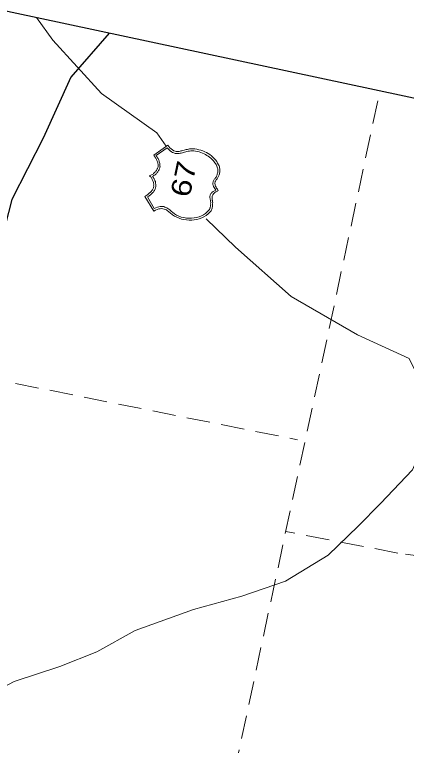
# Model space of a CAD drawing. Extents: x 2363411 to 2369126, y 6976878 to 6988319.
# Drawn here: x 2366047.6 to 2366148.5, y 6977167 to 6977355.3 of the extents above; entities that cross this region are included whole.
import ezdxf

# ---------------------------------------------------------------- set-up
doc = ezdxf.new("R2010")
doc.units = 0
doc.header["$LTSCALE"] = 2
doc.linetypes.add('MEDIUM_DASHED', pattern=[4.5, 3, -1.5])
doc.layers.add('62', color=7, linetype='Continuous', lineweight=13)
doc.layers.add('63', color=7, linetype='Continuous', lineweight=13)

msp = doc.modelspace()

# ---------------------------------------------------------------- linework, layer by layer
at = {"layer": '62', "linetype": 'MEDIUM_DASHED'}
for p, q in [((2366047.7, 6976895.971), (2366141.643, 6977335.641)), ((2365844.834, 6977300.827), (2366120.392, 6977245.768))]:
    msp.add_line(p, q, dxfattribs=at)
at = {"layer": '62'}
msp.add_line((2366084.159, 6977324.84), (2366086.62, 6977321.394), dxfattribs=at)
at = {"layer": '62', "lineweight": 25}
for points in [[(2365678.211, 6976974.92), (2366133.213, 6976877.7), (2366227.156, 6977317.368), (2365772.152, 6977414.588)], [(2366071.953, 6977350.532), (2366062.056, 6977339.206), (2366054.911, 6977323.43), (2366046.839, 6977307.62), (2366040.832, 6977284.562), (2366037.039, 6977271.012), (2366035.805, 6977261.035), (2366034.117, 6977243.885), (2366031.631, 6977232.244), (2366030.337, 6977223.387)]]:
    msp.add_lwpolyline(points, dxfattribs=at)
at = {"layer": '62'}
for points in [[(2366053.162, 6977354.543), (2366057.393, 6977348.718), (2366069.909, 6977334.93), (2366084.159, 6977324.84)], [(2366083.387, 6977304.644), (2366081.122, 6977308.465), (2366081.357, 6977308.599), (2366081.594, 6977308.733), (2366081.789, 6977308.897), (2366082.002, 6977309.034), (2366082.173, 6977309.185), (2366082.346, 6977309.353), (2366082.512, 6977309.479), (2366082.686, 6977309.648), (2366082.833, 6977309.801), (2366082.937, 6977309.965), (2366083.067, 6977310.144), (2366083.148, 6977310.311), (2366083.257, 6977310.494), (2366083.335, 6977310.639), (2366083.377, 6977310.838), (2366083.395, 6977311.039), (2366083.404, 6977311.174), (2366083.371, 6977311.343), (2366083.385, 6977311.524), (2366083.378, 6977311.709), (2366083.329, 6977311.906), (2366083.295, 6977312.073), (2366083.246, 6977312.267), (2366083.196, 6977312.462), (2366083.101, 6977312.666), (2366083.025, 6977312.844), (2366082.901, 6977313.032), (2366082.846, 6977313.204), (2366082.698, 6977313.374), (2366082.568, 6977313.517), (2366082.411, 6977313.642), (2366082.253, 6977313.768), (2366082.453, 6977313.84), (2366082.658, 6977313.937), (2366082.857, 6977314.007), (2366083.043, 6977314.129), (2366083.226, 6977314.227), (2366083.375, 6977314.379), (2366083.54, 6977314.505), (2366083.686, 6977314.658), (2366083.814, 6977314.815), (2366083.961, 6977314.968), (2366084.07, 6977315.151), (2366084.173, 6977315.313), (2366084.262, 6977315.525), (2366084.364, 6977315.665), (2366084.453, 6977315.875), (2366084.496, 6977316.072), (2366084.529, 6977316.227), (2366084.566, 6977316.403), (2366084.533, 6977316.569), (2366084.532, 6977316.778), (2366084.477, 6977316.952), (2366084.447, 6977317.142), (2366084.372, 6977317.32), (2366084.321, 6977317.515), (2366084.222, 6977317.697), (2366084.132, 6977317.923), (2366084.033, 6977318.104), (2366083.939, 6977318.31), (2366083.795, 6977318.5), (2366083.682, 6977318.731), (2366083.535, 6977318.903), (2366083.397, 6977319.115), (2366087.028, 6977321.675), (2366087.25, 6977321.329), (2366087.52, 6977320.972), (2366087.851, 6977320.693), (2366088.193, 6977320.46), (2366088.535, 6977320.228), (2366088.877, 6977320.106), (2366089.158, 6977320.025), (2366089.362, 6977320.002), (2366089.543, 6977319.988), (2366089.736, 6977320.039), (2366089.945, 6977320.039), (2366090.167, 6977320.106), (2366090.408, 6977320.169), (2366090.654, 6977320.235), (2366090.919, 6977320.291), (2366091.21, 6977320.368), (2366091.48, 6977320.449), (2366091.751, 6977320.529), (2366092.06, 6977320.577), (2366092.326, 6977320.635), (2366092.615, 6977320.687), (2366092.871, 6977320.702), (2366093.131, 6977320.741), (2366093.399, 6977320.706), (2366093.969, 6977320.676), (2366094.53, 6977320.604), (2366095.035, 6977320.494), (2366095.553, 6977320.336), (2366096.048, 6977320.183), (2366096.531, 6977319.967), (2366096.992, 6977319.752), (2366097.445, 6977319.496), (2366097.868, 6977319.222), (2366098.262, 6977318.908)], [(2366098.788, 6977317.597), (2366098.582, 6977317.823), (2366098.338, 6977318.084), (2366098.064, 6977318.304), (2366097.771, 6977318.553), (2366097.451, 6977318.779), (2366097.111, 6977319.015), (2366096.746, 6977319.253), (2366096.375, 6977319.448), (2366095.954, 6977319.63), (2366095.528, 6977319.789), (2366095.098, 6977319.928), (2366094.636, 6977320.027), (2366094.146, 6977320.109), (2366093.718, 6977320.153), (2366093.313, 6977320.193), (2366092.943, 6977320.182), (2366092.588, 6977320.141), (2366092.258, 6977320.097), (2366091.921, 6977320.032), (2366091.629, 6977319.957), (2366091.333, 6977319.857), (2366091.035, 6977319.761), (2366090.77, 6977319.701), (2366090.5, 6977319.622), (2366090.235, 6977319.564), (2366089.97, 6977319.506), (2366089.711, 6977319.492), (2366089.478, 6977319.472), (2366089.204, 6977319.484), (2366088.895, 6977319.55), (2366088.554, 6977319.667), (2366088.238, 6977319.807), (2366087.927, 6977319.963), (2366087.626, 6977320.166), (2366087.359, 6977320.43), (2366087.114, 6977320.691), (2366086.875, 6977320.969), (2366084.009, 6977318.962), (2366084.128, 6977318.775), (2366084.256, 6977318.608), (2366084.4, 6977318.418), (2366084.498, 6977318.237), (2366084.593, 6977318.031), (2366084.686, 6977317.827), (2366084.76, 6977317.629), (2366084.83, 6977317.428), (2366084.876, 6977317.212), (2366084.948, 6977317.012), (2366084.993, 6977316.794), (2366085.006, 6977316.632), (2366085.007, 6977316.425), (2366084.997, 6977316.266), (2366085.012, 6977316.123), (2366084.981, 6977315.969), (2366084.948, 6977315.814), (2366084.882, 6977315.622), (2366084.822, 6977315.452), (2366084.762, 6977315.279), (2366084.655, 6977315.093), (2366084.555, 6977314.955), (2366084.447, 6977314.772), (2366084.321, 6977314.614), (2366084.222, 6977314.474), (2366084.065, 6977314.279), (2366083.927, 6977314.169), (2366083.784, 6977314.04), (2366083.617, 6977313.892), (2366083.438, 6977313.813), (2366083.273, 6977313.689), (2366083.046, 6977313.601), (2366083.194, 6977313.43), (2366083.326, 6977313.287), (2366083.424, 6977313.105), (2366083.505, 6977312.948), (2366083.588, 6977312.791), (2366083.648, 6977312.642), (2366083.719, 6977312.444), (2366083.807, 6977312.311), (2366083.811, 6977312.124), (2366083.867, 6977311.953), (2366083.879, 6977311.786), (2366083.911, 6977311.62), (2366083.901, 6977311.461), (2366083.929, 6977311.271), (2366083.919, 6977311.113), (2366083.909, 6977310.952), (2366083.891, 6977310.772), (2366083.844, 6977310.553), (2366083.764, 6977310.388), (2366083.671, 6977310.174), (2366083.563, 6977309.991), (2366083.428, 6977309.789), (2366083.294, 6977309.59), (2366083.15, 6977309.457), (2366082.995, 6977309.261), (2366082.843, 6977309.087), (2366082.673, 6977308.94), (2366082.484, 6977308.818), (2366082.31, 6977308.649), (2366082.101, 6977308.532)], [(2366098.262, 6977318.908), (2366098.626, 6977318.575), (2366098.967, 6977318.226), (2366099.303, 6977317.857), (2366099.601, 6977317.426), (2366099.855, 6977317.001), (2366100.106, 6977316.557), (2366100.213, 6977316.303), (2366100.299, 6977316.056), (2366100.36, 6977315.811), (2366100.378, 6977315.579), (2366100.425, 6977315.362), (2366100.424, 6977315.131), (2366100.416, 6977314.879), (2366100.395, 6977314.679), (2366100.371, 6977314.453), (2366100.3, 6977314.237), (2366100.258, 6977314.042), (2366100.174, 6977313.851), (2366100.058, 6977313.647), (2366099.999, 6977313.473), (2366099.895, 6977313.314), (2366099.793, 6977313.149), (2366099.688, 6977312.988), (2366099.589, 6977312.847), (2366099.466, 6977312.714), (2366099.392, 6977312.566), (2366099.314, 6977312.423), (2366099.233, 6977312.257), (2366099.179, 6977312.107), (2366099.141, 6977311.93), (2366099.148, 6977311.745), (2366099.176, 6977311.555), (2366099.243, 6977311.334), (2366099.315, 6977311.135), (2366099.441, 6977310.854), (2366099.566, 6977310.598), (2366099.787, 6977310.32), (2366100.012, 6977309.973), (2366099.696, 6977309.787), (2366099.423, 6977309.594), (2366099.16, 6977309.444), (2366098.988, 6977309.272), (2366098.818, 6977309.124), (2366098.669, 6977308.972), (2366098.593, 6977308.827), (2366098.494, 6977308.688), (2366098.443, 6977308.558), (2366098.41, 6977308.406), (2366098.408, 6977308.289), (2366098.419, 6977308.128), (2366098.413, 6977307.992), (2366098.429, 6977307.849), (2366098.463, 6977307.683), (2366098.473, 6977307.519), (2366098.518, 6977307.395), (2366098.522, 6977307.21), (2366098.552, 6977307.019), (2366098.579, 6977306.829), (2366098.56, 6977306.625), (2366098.567, 6977306.441), (2366098.562, 6977306.211), (2366098.547, 6977306.031), (2366098.499, 6977305.81), (2366098.462, 6977305.634), (2366098.416, 6977305.414), (2366098.341, 6977305.177), (2366098.233, 6977304.993), (2366098.142, 6977304.782), (2366098.009, 6977304.581), (2366097.848, 6977304.384), (2366097.412, 6977303.95), (2366096.889, 6977303.552), (2366096.335, 6977303.21), (2366095.744, 6977302.923), (2366095.118, 6977302.689), (2366094.508, 6977302.521), (2366093.845, 6977302.432), (2366093.163, 6977302.371), (2366092.518, 6977302.369), (2366091.856, 6977302.394), (2366091.188, 6977302.494), (2366090.55, 6977302.631), (2366089.905, 6977302.836), (2366089.332, 6977303.075), (2366088.756, 6977303.382), (2366088.23, 6977303.723), (2366088.029, 6977303.856), (2366087.832, 6977304.015), (2366087.618, 6977304.2), (2366087.408, 6977304.406), (2366087.17, 6977304.572), (2366086.934, 6977304.759), (2366086.677, 6977304.955), (2366086.399, 6977305.057), (2366086.103, 6977305.19), (2366085.775, 6977305.26), (2366085.466, 6977305.326), (2366085.09, 6977305.292), (2366084.714, 6977305.256), (2366084.271, 6977305.121)], [(2366081.761, 6977308.331), (2366083.533, 6977305.326), (2366083.968, 6977305.532), (2366084.362, 6977305.654), (2366084.73, 6977305.76), (2366085.066, 6977305.827), (2366085.41, 6977305.823), (2366085.711, 6977305.826), (2366085.984, 6977305.815), (2366086.262, 6977305.71), (2366086.533, 6977305.583), (2366086.789, 6977305.481), (2366087.056, 6977305.332), (2366087.29, 6977305.143), (2366087.509, 6977304.984), (2366087.747, 6977304.794), (2366087.952, 6977304.588), (2366088.186, 6977304.379), (2366088.718, 6977303.965), (2366089.293, 6977303.635), (2366089.852, 6977303.354), (2366090.477, 6977303.151), (2366091.134, 6977302.988), (2366091.797, 6977302.869), (2366092.459, 6977302.842), (2366093.109, 6977302.865), (2366093.79, 6977302.926), (2366094.439, 6977303.063), (2366095.073, 6977303.228), (2366095.675, 6977303.468), (2366096.195, 6977303.75), (2366096.748, 6977304.067), (2366097.197, 6977304.454), (2366097.609, 6977304.873), (2366097.654, 6977304.978), (2366097.744, 6977305.075), (2366097.822, 6977305.218), (2366097.859, 6977305.396), (2366097.887, 6977305.527), (2366097.947, 6977305.7), (2366097.985, 6977305.875), (2366098.001, 6977306.055), (2366098.042, 6977306.253), (2366098.08, 6977306.429), (2366098.052, 6977306.619), (2366098.067, 6977306.8), (2366098.082, 6977306.981), (2366098.049, 6977307.149), (2366098.038, 6977307.313), (2366098.022, 6977307.454), (2366097.968, 6977307.627), (2366097.93, 6977307.772), (2366097.892, 6977307.919), (2366097.877, 6977308.059), (2366097.849, 6977308.249), (2366097.85, 6977308.366), (2366097.859, 6977308.523), (2366097.892, 6977308.678), (2366097.948, 6977308.829), (2366098.039, 6977309.037), (2366098.139, 6977309.177), (2366098.307, 6977309.327), (2366098.464, 6977309.523), (2366098.732, 6977309.697), (2366099.008, 6977309.912), (2366099.346, 6977310.093), (2366099.105, 6977310.466), (2366098.94, 6977310.779), (2366098.79, 6977311.042), (2366098.687, 6977311.316), (2366098.646, 6977311.556), (2366098.617, 6977311.744), (2366098.616, 6977311.951), (2366098.658, 6977312.15), (2366098.718, 6977312.322), (2366098.772, 6977312.472), (2366098.876, 6977312.631), (2366098.98, 6977312.795), (2366099.082, 6977312.955), (2366099.205, 6977313.091), (2366099.312, 6977313.275), (2366099.443, 6977313.455), (2366099.529, 6977313.643), (2366099.659, 6977313.822), (2366099.706, 6977314.043), (2366099.771, 6977314.236), (2366099.841, 6977314.45), (2366099.865, 6977314.676), (2366099.885, 6977314.878), (2366099.911, 6977315.104), (2366099.885, 6977315.314), (2366099.889, 6977315.546), (2366099.801, 6977315.772), (2366099.759, 6977316.009), (2366099.666, 6977316.215), (2366099.58, 6977316.463), (2366099.445, 6977316.698), (2366099.312, 6977316.933), (2366099.168, 6977317.124), (2366098.965, 6977317.353), (2366098.788, 6977317.597)], [(2366082.101, 6977308.532), (2366081.92, 6977308.432), (2366081.761, 6977308.331)], [(2366084.271, 6977305.121), (2366083.842, 6977304.937), (2366083.387, 6977304.644)], [(2366096.932, 6977302.67), (2366104.486, 6977295.374), (2366118.795, 6977282.65), (2366135.856, 6977272.793), (2366149.213, 6977266.718), (2366158.553, 6977247.649), (2366168.364, 6977245.412), (2366174.148, 6977227.473), (2366180.022, 6977212.757), (2366183.73, 6977195.536), (2366183.185, 6977172.733), (2366183.468, 6977153.162), (2366184.402, 6977131.701), (2366184.733, 6977118.813)], [(2366165.563, 6977270.54), (2366160.925, 6977263.273), (2366157.11, 6977254.238), (2366150.016, 6977238.06), (2366141.756, 6977229.335), (2366136.001, 6977223.497), (2366128.351, 6977216.018), (2366117.334, 6977209.377), (2366106.082, 6977205.501), (2366093.663, 6977202.078), (2366078.646, 6977196.636), (2366068.712, 6977191.165), (2366059.206, 6977187.374), (2366047.443, 6977183.467), (2366041.833, 6977180.594), (2366027.902, 6977176.345)]]:
    msp.add_lwpolyline(points, dxfattribs=at)
at = {"layer": '62', "linetype": 'MEDIUM_DASHED'}
msp.add_lwpolyline([(2366203.686, 6977207.519), (2366189.861, 6977210.657), (2366146.236, 6977216.593), (2366117.386, 6977222.114)], dxfattribs=at)
at = {"layer": '63', "linetype": 'MEDIUM_DASHED'}
for p, q in [((2366047.7, 6976895.971), (2366141.643, 6977335.641)), ((2365844.834, 6977300.827), (2366120.392, 6977245.768))]:
    msp.add_line(p, q, dxfattribs=at)
at = {"layer": '63'}
msp.add_line((2366084.159, 6977324.84), (2366086.62, 6977321.394), dxfattribs=at)
at = {"layer": '63', "lineweight": 25}
for points in [[(2365678.211, 6976974.92), (2366133.213, 6976877.7), (2366227.156, 6977317.368), (2365772.152, 6977414.588)], [(2366071.953, 6977350.532), (2366062.056, 6977339.206), (2366054.911, 6977323.43), (2366046.839, 6977307.62), (2366040.832, 6977284.562), (2366037.039, 6977271.012), (2366035.805, 6977261.035), (2366034.117, 6977243.885), (2366031.631, 6977232.244), (2366030.337, 6977223.387)]]:
    msp.add_lwpolyline(points, dxfattribs=at)
at = {"layer": '63'}
for points in [[(2366053.162, 6977354.543), (2366057.393, 6977348.718), (2366069.909, 6977334.93), (2366084.159, 6977324.84)], [(2366083.387, 6977304.644), (2366081.122, 6977308.465), (2366081.357, 6977308.599), (2366081.594, 6977308.733), (2366081.789, 6977308.897), (2366082.002, 6977309.034), (2366082.173, 6977309.185), (2366082.346, 6977309.353), (2366082.512, 6977309.479), (2366082.686, 6977309.648), (2366082.833, 6977309.801), (2366082.937, 6977309.965), (2366083.067, 6977310.144), (2366083.148, 6977310.311), (2366083.257, 6977310.494), (2366083.335, 6977310.639), (2366083.377, 6977310.838), (2366083.395, 6977311.039), (2366083.404, 6977311.174), (2366083.371, 6977311.343), (2366083.385, 6977311.524), (2366083.378, 6977311.709), (2366083.329, 6977311.906), (2366083.295, 6977312.073), (2366083.246, 6977312.267), (2366083.196, 6977312.462), (2366083.101, 6977312.666), (2366083.025, 6977312.844), (2366082.901, 6977313.032), (2366082.846, 6977313.204), (2366082.698, 6977313.374), (2366082.568, 6977313.517), (2366082.411, 6977313.642), (2366082.253, 6977313.768), (2366082.453, 6977313.84), (2366082.658, 6977313.937), (2366082.857, 6977314.007), (2366083.043, 6977314.129), (2366083.226, 6977314.227), (2366083.375, 6977314.379), (2366083.54, 6977314.505), (2366083.686, 6977314.658), (2366083.814, 6977314.815), (2366083.961, 6977314.968), (2366084.07, 6977315.151), (2366084.173, 6977315.313), (2366084.262, 6977315.525), (2366084.364, 6977315.665), (2366084.453, 6977315.875), (2366084.496, 6977316.072), (2366084.529, 6977316.227), (2366084.566, 6977316.403), (2366084.533, 6977316.569), (2366084.532, 6977316.778), (2366084.477, 6977316.952), (2366084.447, 6977317.142), (2366084.372, 6977317.32), (2366084.321, 6977317.515), (2366084.222, 6977317.697), (2366084.132, 6977317.923), (2366084.033, 6977318.104), (2366083.939, 6977318.31), (2366083.795, 6977318.5), (2366083.682, 6977318.731), (2366083.535, 6977318.903), (2366083.397, 6977319.115), (2366087.028, 6977321.675), (2366087.25, 6977321.329), (2366087.52, 6977320.972), (2366087.851, 6977320.693), (2366088.193, 6977320.46), (2366088.535, 6977320.228), (2366088.877, 6977320.106), (2366089.158, 6977320.025), (2366089.362, 6977320.002), (2366089.543, 6977319.988), (2366089.736, 6977320.039), (2366089.945, 6977320.039), (2366090.167, 6977320.106), (2366090.408, 6977320.169), (2366090.654, 6977320.235), (2366090.919, 6977320.291), (2366091.21, 6977320.368), (2366091.48, 6977320.449), (2366091.751, 6977320.529), (2366092.06, 6977320.577), (2366092.326, 6977320.635), (2366092.615, 6977320.687), (2366092.871, 6977320.702), (2366093.131, 6977320.741), (2366093.399, 6977320.706), (2366093.969, 6977320.676), (2366094.53, 6977320.604), (2366095.035, 6977320.494), (2366095.553, 6977320.336), (2366096.048, 6977320.183), (2366096.531, 6977319.967), (2366096.992, 6977319.752), (2366097.445, 6977319.496), (2366097.868, 6977319.222), (2366098.262, 6977318.908)], [(2366098.788, 6977317.597), (2366098.582, 6977317.823), (2366098.338, 6977318.084), (2366098.064, 6977318.304), (2366097.771, 6977318.553), (2366097.451, 6977318.779), (2366097.111, 6977319.015), (2366096.746, 6977319.253), (2366096.375, 6977319.448), (2366095.954, 6977319.63), (2366095.528, 6977319.789), (2366095.098, 6977319.928), (2366094.636, 6977320.027), (2366094.146, 6977320.109), (2366093.718, 6977320.153), (2366093.313, 6977320.193), (2366092.943, 6977320.182), (2366092.588, 6977320.141), (2366092.258, 6977320.097), (2366091.921, 6977320.032), (2366091.629, 6977319.957), (2366091.333, 6977319.857), (2366091.035, 6977319.761), (2366090.77, 6977319.701), (2366090.5, 6977319.622), (2366090.235, 6977319.564), (2366089.97, 6977319.506), (2366089.711, 6977319.492), (2366089.478, 6977319.472), (2366089.204, 6977319.484), (2366088.895, 6977319.55), (2366088.554, 6977319.667), (2366088.238, 6977319.807), (2366087.927, 6977319.963), (2366087.626, 6977320.166), (2366087.359, 6977320.43), (2366087.114, 6977320.691), (2366086.875, 6977320.969), (2366084.009, 6977318.962), (2366084.128, 6977318.775), (2366084.256, 6977318.608), (2366084.4, 6977318.418), (2366084.498, 6977318.237), (2366084.593, 6977318.031), (2366084.686, 6977317.827), (2366084.76, 6977317.629), (2366084.83, 6977317.428), (2366084.876, 6977317.212), (2366084.948, 6977317.012), (2366084.993, 6977316.794), (2366085.006, 6977316.632), (2366085.007, 6977316.425), (2366084.997, 6977316.266), (2366085.012, 6977316.123), (2366084.981, 6977315.969), (2366084.948, 6977315.814), (2366084.882, 6977315.622), (2366084.822, 6977315.452), (2366084.762, 6977315.279), (2366084.655, 6977315.093), (2366084.555, 6977314.955), (2366084.447, 6977314.772), (2366084.321, 6977314.614), (2366084.222, 6977314.474), (2366084.065, 6977314.279), (2366083.927, 6977314.169), (2366083.784, 6977314.04), (2366083.617, 6977313.892), (2366083.438, 6977313.813), (2366083.273, 6977313.689), (2366083.046, 6977313.601), (2366083.194, 6977313.43), (2366083.326, 6977313.287), (2366083.424, 6977313.105), (2366083.505, 6977312.948), (2366083.588, 6977312.791), (2366083.648, 6977312.642), (2366083.719, 6977312.444), (2366083.807, 6977312.311), (2366083.811, 6977312.124), (2366083.867, 6977311.953), (2366083.879, 6977311.786), (2366083.911, 6977311.62), (2366083.901, 6977311.461), (2366083.929, 6977311.271), (2366083.919, 6977311.113), (2366083.909, 6977310.952), (2366083.891, 6977310.772), (2366083.844, 6977310.553), (2366083.764, 6977310.388), (2366083.671, 6977310.174), (2366083.563, 6977309.991), (2366083.428, 6977309.789), (2366083.294, 6977309.59), (2366083.15, 6977309.457), (2366082.995, 6977309.261), (2366082.843, 6977309.087), (2366082.673, 6977308.94), (2366082.484, 6977308.818), (2366082.31, 6977308.649), (2366082.101, 6977308.532)], [(2366098.262, 6977318.908), (2366098.626, 6977318.575), (2366098.967, 6977318.226), (2366099.303, 6977317.857), (2366099.601, 6977317.426), (2366099.855, 6977317.001), (2366100.106, 6977316.557), (2366100.213, 6977316.303), (2366100.299, 6977316.056), (2366100.36, 6977315.811), (2366100.378, 6977315.579), (2366100.425, 6977315.362), (2366100.424, 6977315.131), (2366100.416, 6977314.879), (2366100.395, 6977314.679), (2366100.371, 6977314.453), (2366100.3, 6977314.237), (2366100.258, 6977314.042), (2366100.174, 6977313.851), (2366100.058, 6977313.647), (2366099.999, 6977313.473), (2366099.895, 6977313.314), (2366099.793, 6977313.149), (2366099.688, 6977312.988), (2366099.589, 6977312.847), (2366099.466, 6977312.714), (2366099.392, 6977312.566), (2366099.314, 6977312.423), (2366099.233, 6977312.257), (2366099.179, 6977312.107), (2366099.141, 6977311.93), (2366099.148, 6977311.745), (2366099.176, 6977311.555), (2366099.243, 6977311.334), (2366099.315, 6977311.135), (2366099.441, 6977310.854), (2366099.566, 6977310.598), (2366099.787, 6977310.32), (2366100.012, 6977309.973), (2366099.696, 6977309.787), (2366099.423, 6977309.594), (2366099.16, 6977309.444), (2366098.988, 6977309.272), (2366098.818, 6977309.124), (2366098.669, 6977308.972), (2366098.593, 6977308.827), (2366098.494, 6977308.688), (2366098.443, 6977308.558), (2366098.41, 6977308.406), (2366098.408, 6977308.289), (2366098.419, 6977308.128), (2366098.413, 6977307.992), (2366098.429, 6977307.849), (2366098.463, 6977307.683), (2366098.473, 6977307.519), (2366098.518, 6977307.395), (2366098.522, 6977307.21), (2366098.552, 6977307.019), (2366098.579, 6977306.829), (2366098.56, 6977306.625), (2366098.567, 6977306.441), (2366098.562, 6977306.211), (2366098.547, 6977306.031), (2366098.499, 6977305.81), (2366098.462, 6977305.634), (2366098.416, 6977305.414), (2366098.341, 6977305.177), (2366098.233, 6977304.993), (2366098.142, 6977304.782), (2366098.009, 6977304.581), (2366097.848, 6977304.384), (2366097.412, 6977303.95), (2366096.889, 6977303.552), (2366096.335, 6977303.21), (2366095.744, 6977302.923), (2366095.118, 6977302.689), (2366094.508, 6977302.521), (2366093.845, 6977302.432), (2366093.163, 6977302.371), (2366092.518, 6977302.369), (2366091.856, 6977302.394), (2366091.188, 6977302.494), (2366090.55, 6977302.631), (2366089.905, 6977302.836), (2366089.332, 6977303.075), (2366088.756, 6977303.382), (2366088.23, 6977303.723), (2366088.029, 6977303.856), (2366087.832, 6977304.015), (2366087.618, 6977304.2), (2366087.408, 6977304.406), (2366087.17, 6977304.572), (2366086.934, 6977304.759), (2366086.677, 6977304.955), (2366086.399, 6977305.057), (2366086.103, 6977305.19), (2366085.775, 6977305.26), (2366085.466, 6977305.326), (2366085.09, 6977305.292), (2366084.714, 6977305.256), (2366084.271, 6977305.121)], [(2366081.761, 6977308.331), (2366083.533, 6977305.326), (2366083.968, 6977305.532), (2366084.362, 6977305.654), (2366084.73, 6977305.76), (2366085.066, 6977305.827), (2366085.41, 6977305.823), (2366085.711, 6977305.826), (2366085.984, 6977305.815), (2366086.262, 6977305.71), (2366086.533, 6977305.583), (2366086.789, 6977305.481), (2366087.056, 6977305.332), (2366087.29, 6977305.143), (2366087.509, 6977304.984), (2366087.747, 6977304.794), (2366087.952, 6977304.588), (2366088.186, 6977304.379), (2366088.718, 6977303.965), (2366089.293, 6977303.635), (2366089.852, 6977303.354), (2366090.477, 6977303.151), (2366091.134, 6977302.988), (2366091.797, 6977302.869), (2366092.459, 6977302.842), (2366093.109, 6977302.865), (2366093.79, 6977302.926), (2366094.439, 6977303.063), (2366095.073, 6977303.228), (2366095.675, 6977303.468), (2366096.195, 6977303.75), (2366096.748, 6977304.067), (2366097.197, 6977304.454), (2366097.609, 6977304.873), (2366097.654, 6977304.978), (2366097.744, 6977305.075), (2366097.822, 6977305.218), (2366097.859, 6977305.396), (2366097.887, 6977305.527), (2366097.947, 6977305.7), (2366097.985, 6977305.875), (2366098.001, 6977306.055), (2366098.042, 6977306.253), (2366098.08, 6977306.429), (2366098.052, 6977306.619), (2366098.067, 6977306.8), (2366098.082, 6977306.981), (2366098.049, 6977307.149), (2366098.038, 6977307.313), (2366098.022, 6977307.454), (2366097.968, 6977307.627), (2366097.93, 6977307.772), (2366097.892, 6977307.919), (2366097.877, 6977308.059), (2366097.849, 6977308.249), (2366097.85, 6977308.366), (2366097.859, 6977308.523), (2366097.892, 6977308.678), (2366097.948, 6977308.829), (2366098.039, 6977309.037), (2366098.139, 6977309.177), (2366098.307, 6977309.327), (2366098.464, 6977309.523), (2366098.732, 6977309.697), (2366099.008, 6977309.912), (2366099.346, 6977310.093), (2366099.105, 6977310.466), (2366098.94, 6977310.779), (2366098.79, 6977311.042), (2366098.687, 6977311.316), (2366098.646, 6977311.556), (2366098.617, 6977311.744), (2366098.616, 6977311.951), (2366098.658, 6977312.15), (2366098.718, 6977312.322), (2366098.772, 6977312.472), (2366098.876, 6977312.631), (2366098.98, 6977312.795), (2366099.082, 6977312.955), (2366099.205, 6977313.091), (2366099.312, 6977313.275), (2366099.443, 6977313.455), (2366099.529, 6977313.643), (2366099.659, 6977313.822), (2366099.706, 6977314.043), (2366099.771, 6977314.236), (2366099.841, 6977314.45), (2366099.865, 6977314.676), (2366099.885, 6977314.878), (2366099.911, 6977315.104), (2366099.885, 6977315.314), (2366099.889, 6977315.546), (2366099.801, 6977315.772), (2366099.759, 6977316.009), (2366099.666, 6977316.215), (2366099.58, 6977316.463), (2366099.445, 6977316.698), (2366099.312, 6977316.933), (2366099.168, 6977317.124), (2366098.965, 6977317.353), (2366098.788, 6977317.597)], [(2366082.101, 6977308.532), (2366081.92, 6977308.432), (2366081.761, 6977308.331)], [(2366084.271, 6977305.121), (2366083.842, 6977304.937), (2366083.387, 6977304.644)], [(2366096.932, 6977302.67), (2366104.486, 6977295.374), (2366118.795, 6977282.65), (2366135.856, 6977272.793), (2366149.213, 6977266.718), (2366158.553, 6977247.649), (2366168.364, 6977245.412), (2366174.148, 6977227.473), (2366180.022, 6977212.757), (2366183.73, 6977195.536), (2366183.185, 6977172.733), (2366183.468, 6977153.162), (2366184.402, 6977131.701), (2366184.733, 6977118.813)], [(2366165.563, 6977270.54), (2366160.925, 6977263.273), (2366157.11, 6977254.238), (2366150.016, 6977238.06), (2366141.756, 6977229.335), (2366136.001, 6977223.497), (2366128.351, 6977216.018), (2366117.334, 6977209.377), (2366106.082, 6977205.501), (2366093.663, 6977202.078), (2366078.646, 6977196.636), (2366068.712, 6977191.165), (2366059.206, 6977187.374), (2366047.443, 6977183.467), (2366041.833, 6977180.594), (2366027.902, 6977176.345)]]:
    msp.add_lwpolyline(points, dxfattribs=at)
at = {"layer": '63', "linetype": 'MEDIUM_DASHED'}
msp.add_lwpolyline([(2366203.686, 6977207.519), (2366189.861, 6977210.657), (2366146.236, 6977216.593), (2366117.386, 6977222.114)], dxfattribs=at)

# ---------------------------------------------------------------- texts
at = {"layer": '62', "width": 1.2}
msp.add_text('67', height=5.099, rotation=77.939, dxfattribs=at).set_placement((2366092.61, 6977307.966))
at = {"layer": '63', "width": 1.2}
msp.add_text('67', height=5.099, rotation=77.939, dxfattribs=at).set_placement((2366092.61, 6977307.966))

doc.saveas('drawing.dxf')
